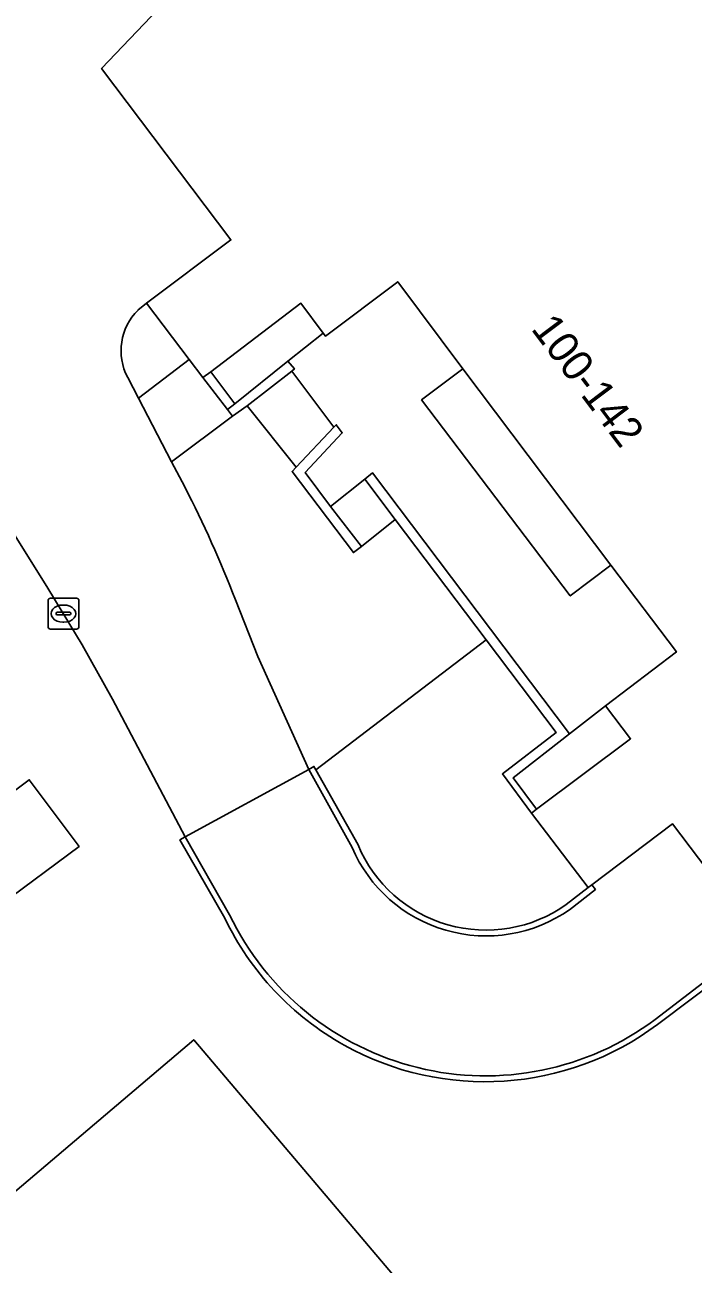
# Model space of a CAD drawing. Extents: x 159664 to 160323, y 385312 to 386115.
# Drawn here: x 160248.41 to 160270.1, y 385679.17 to 385719.4 of the extents above; entities that cross this region are included whole.
import ezdxf

# ---------------------------------------------------------------- set-up
doc = ezdxf.new("R2010")
doc.units = 0
for name, color, linetype in [('IMGEO_Erf', 7, 'Continuous'), ('IMGEO_Grasland_overig', 7, 'Continuous'), ('IMGEO_Groenvoorziening', 7, 'Continuous'), ('IMGEO_Kolk', 7, 'Continuous'), ('IMGEO_Muur', 7, 'Continuous'), ('IMGEO_Pand', 7, 'Continuous'), ('IMGEO_Pand_nummerreeks', 7, 'Continuous'), ('IMGEO_Rijbaan_lokaal_gesloten', 7, 'Continuous'), ('IMGEO_Rijbaan_lokaal_open', 7, 'Continuous'), ('IMGEO_Voetpad_gesloten', 7, 'Continuous'), ('IMGEO_Voetpad_open', 7, 'Continuous')]:
    doc.layers.add(name, color=color, linetype=linetype)

msp = doc.modelspace()

# ---------------------------------------------------------------- linework, layer by layer
at = {"layer": 'IMGEO_Erf'}
for points in [[(160266.876, 385735.19), (160264.393, 385733.512), (160252.585, 385725.7), (160246.042, 385721.322), (160246.807, 385720.18), (160248.245, 385721.253), (160251.326, 385723.587), (160252.567, 385721.898), (160255.554, 385725.077), (160256.651, 385724.048), (160264.426, 385732.287), (160272.75, 385724.372), (160285.704, 385707.218), (160290.989, 385697.019), (160273.623, 385687.905), (160272.395, 385689.541), (160268.944, 385686.952)], [(160254.898, 385690.405), (160253.446, 385692.943), (160253.619, 385693.044), (160251.255, 385697.508), (160250.277, 385699.271), (160249.155, 385701.115), (160239.467, 385716.612), (160239.203, 385716.432), (160229.319, 385709.686), (160228.116, 385708.9), (160194.996, 385688.17)], [(160226.855, 385676.268), (160230.745, 385679.398), (160229.115, 385681.462), (160231.74, 385683.535), (160234.236, 385685.506), (160235.866, 385683.442), (160239.809, 385686.456), (160238.134, 385688.577), (160240.759, 385690.65), (160243.454, 385692.779), (160245.129, 385690.658), (160246.77, 385691.949), (160245.996, 385692.985), (160248.554, 385694.896), (160250.173, 385692.729), (160247.615, 385690.818), (160213.723, 385664.117)], [(160240.294, 385673.867), (160246.675, 385680.3), (160246.795, 385680.421), (160253.895, 385686.456), (160257.769, 385681.887), (160261.002, 385678.073)]]:
    msp.add_lwpolyline(points, dxfattribs=at)
for centre, radius, start, end in [((160263.334, 385694.452), 9.357, 205.6268, 240.8523), ((160263.342, 385694.461), 9.369, 240.8394, 306.7237)]:
    msp.add_arc(centre, radius, start, end, dxfattribs=at)
at = {"layer": 'IMGEO_Grasland_overig'}
for points in [[(160251.749, 385707.952), (160252.097, 385707.282), (160253.747, 385708.533), (160252.363, 385710.359)], [(160252.363, 385710.359), (160252.084, 385710.136)]]:
    msp.add_lwpolyline(points, dxfattribs=at)
msp.add_arc((160253.38, 385708.82), 1.847, 134.5457, 208.0133, dxfattribs=at)
at = {"layer": 'IMGEO_Groenvoorziening'}
msp.add_lwpolyline([(160265.982, 385690.843), (160266.688, 385691.397), (160264.855, 385693.81), (160263.909, 385695.081), (160265.653, 385696.432), (160263.384, 385699.436), (160257.849, 385695.219), (160259.223, 385692.78)], dxfattribs=at)
msp.add_arc((160263.376, 385694.512), 4.5, 202.6371, 305.3803, dxfattribs=at)
at = {"layer": 'IMGEO_Kolk'}
for p, q in [((160249.165, 385699.859), (160249.165, 385700.711)), ((160249.24, 385700.785), (160250.092, 385700.785)), ((160249.653, 385700.565), (160249.678, 385700.565)), ((160250.166, 385700.711), (160250.166, 385699.859)), ((160249.424, 385700.279), (160249.424, 385700.291)), ((160249.862, 385700.242), (160249.464, 385700.242)), ((160249.467, 385700.328), (160249.865, 385700.328)), ((160249.908, 385700.291), (160249.908, 385700.279)), ((160250.092, 385699.785), (160249.24, 385699.785)), ((160249.676, 385700.005), (160249.651, 385700.005))]:
    msp.add_line(p, q, dxfattribs=at)
for points in [[(160249.165, 385699.859), (160249.165, 385700.711)], [(160249.24, 385700.785), (160250.092, 385700.785)], [(160250.166, 385700.711), (160250.166, 385699.859)], [(160250.092, 385699.785), (160249.24, 385699.785)]]:
    msp.add_lwpolyline(points, dxfattribs=at)
for centre, radius, start, end in [((160249.242, 385700.709), 0.0765, 91.552, 178.448), ((160249.242, 385700.709), 0.0765, 91.552, 178.448), ((160250.09, 385700.709), 0.0765, 1.552, 88.448), ((160250.09, 385700.709), 0.0765, 1.552, 88.448), ((160249.464, 385700.288), 0.0403, 85.8775, 175.7526), ((160249.461, 385700.278), 0.0366, 178.938, 274.7102), ((160249.865, 385700.285), 0.043, 264.8664, 352.4533), ((160249.869, 385700.29), 0.0386, 1.7309, 96.639), ((160249.242, 385699.861), 0.0765, 181.552, 268.448), ((160249.242, 385699.861), 0.0765, 181.552, 268.448), ((160250.09, 385699.861), 0.0765, 271.552, 358.448), ((160250.09, 385699.861), 0.0765, 271.552, 358.448)]:
    msp.add_arc(centre, radius, start, end, dxfattribs=at)
for centre, major_axis, ratio, start_param, end_param in [((160249.652, 385700.285), (-0.387, 0.002), 0.722429, 4.712389, 7.853982), ((160249.677, 385700.285), (-0.39, 0.002), 0.717154, 1.570796, 4.712389)]:
    msp.add_ellipse(centre, major_axis=major_axis, ratio=ratio, start_param=start_param, end_param=end_param, dxfattribs=at)
at = {"layer": 'IMGEO_Muur'}
for points in [[(160254.985, 385706.906), (160255.221, 385707.094), (160254.446, 385708.137), (160254.188, 385707.952)], [(160254.985, 385706.906), (160255.146, 385706.693), (160255.625, 385707.029), (160257.074, 385708.159), (160257.159, 385708.225), (160256.951, 385708.478), (160255.221, 385707.094)], [(160259.331, 385702.462), (160258.328, 385703.766), (160257.513, 385704.865), (160258.712, 385706.152), (160258.518, 385706.414), (160258.439, 385706.341), (160257.212, 385705.038), (160257.086, 385704.895), (160259.073, 385702.267)], [(160264.259, 385694.957), (160266.084, 385696.384), (160259.698, 385704.854), (160259.447, 385704.653), (160260.425, 385703.336), (160263.384, 385699.436), (160265.653, 385696.432), (160263.909, 385695.081), (160264.855, 385693.81), (160265.013, 385693.938)]]:
    msp.add_lwpolyline(points, close=True, dxfattribs=at)
for points in [[(160259.223, 385692.78), (160257.849, 385695.219), (160257.79, 385695.324), (160257.623, 385695.23), (160259.029, 385692.698)], [(160255.057, 385690.514), (160253.619, 385693.044), (160253.446, 385692.943), (160254.898, 385690.405)], [(160266.088, 385690.674), (160266.924, 385691.335), (160266.805, 385691.485), (160266.688, 385691.397), (160265.982, 385690.843)], [(160268.944, 385686.952), (160272.395, 385689.541), (160272.263, 385689.716), (160268.868, 385687.112)]]:
    msp.add_lwpolyline(points, dxfattribs=at)
for centre, radius, start, end in [((160263.382, 385694.559), 4.734, 203.1436, 304.8585), ((160263.376, 385694.512), 4.5, 202.6371, 305.3803), ((160263.361, 385694.491), 9.208, 205.5922, 306.732), ((160263.334, 385694.452), 9.357, 205.6268, 240.8523), ((160263.342, 385694.461), 9.369, 240.8394, 306.7237)]:
    msp.add_arc(centre, radius, start, end, dxfattribs=at)
at = {"layer": 'IMGEO_Pand'}
msp.add_lwpolyline([(160253.653, 385720.876), (160250.901, 385717.977), (160255.097, 385712.417), (160252.363, 385710.359), (160253.747, 385708.533), (160254.188, 385707.952), (160254.446, 385708.137), (160257.373, 385710.36), (160258.096, 385709.393), (160258.169, 385709.285), (160260.51, 385711.056), (160262.626, 385708.229), (160267.431, 385701.856), (160269.553, 385699.045), (160267.251, 385697.297), (160268.068, 385696.224), (160265.013, 385693.938), (160264.855, 385693.81), (160266.688, 385691.397), (160266.805, 385691.485), (160269.422, 385693.466), (160272.263, 385689.716)], dxfattribs=at)
for points in [[(160245.996, 385692.985), (160246.77, 385691.949), (160247.615, 385690.818), (160250.173, 385692.729), (160248.554, 385694.896)], [(160246.795, 385680.421), (160246.675, 385680.3), (160253.875, 385673.165), (160253.99, 385673.285), (160255.014, 385674.142), (160256.003, 385674.971), (160257.873, 385676.575), (160258.448, 385675.907), (160261.002, 385678.073), (160257.769, 385681.887), (160253.895, 385686.456)]]:
    msp.add_lwpolyline(points, close=True, dxfattribs=at)
at = {"layer": 'IMGEO_Rijbaan_lokaal_gesloten'}
for points in [[(160259.029, 385692.698), (160257.623, 385695.23), (160253.619, 385693.044), (160255.057, 385690.514)], [(160268.868, 385687.112), (160272.263, 385689.716), (160269.422, 385693.466), (160266.805, 385691.485), (160266.924, 385691.335), (160266.088, 385690.674)]]:
    msp.add_lwpolyline(points, dxfattribs=at)
for centre, radius, start, end in [((160263.382, 385694.559), 4.734, 203.1436, 304.8585), ((160263.361, 385694.491), 9.208, 205.5922, 306.732)]:
    msp.add_arc(centre, radius, start, end, dxfattribs=at)
at = {"layer": 'IMGEO_Rijbaan_lokaal_open'}
for points in [[(160252.084, 385710.136), (160252.363, 385710.359), (160255.097, 385712.417), (160250.901, 385717.977), (160253.653, 385720.876), (160252.789, 385721.677), (160252.567, 385721.898), (160251.326, 385723.587), (160248.245, 385721.253), (160246.807, 385720.18), (160246.984, 385719.914), (160245.557, 385718.959), (160244.747, 385720.17), (160239.467, 385716.612), (160249.155, 385701.115), (160250.277, 385699.271), (160251.255, 385697.508), (160253.619, 385693.044), (160257.623, 385695.23), (160255.973, 385698.889), (160255.245, 385700.732)], [(160253.602, 385704.399), (160253.174, 385705.209), (160252.097, 385707.282), (160251.749, 385707.952)]]:
    msp.add_lwpolyline(points, dxfattribs=at)
for centre, radius, start, end in [((160253.38, 385708.82), 1.847, 134.5457, 208.0133), ((160220.574, 385687.399), 37.147, 21.0343, 27.2352)]:
    msp.add_arc(centre, radius, start, end, dxfattribs=at)
at = {"layer": 'IMGEO_Voetpad_gesloten'}
for points in [[(160256.951, 385708.478), (160258.096, 385709.393), (160257.373, 385710.36), (160254.446, 385708.137), (160255.221, 385707.094)], [(160257.212, 385705.038), (160258.439, 385706.341), (160257.074, 385708.159), (160255.625, 385707.029)], [(160260.425, 385703.336), (160259.447, 385704.653), (160258.328, 385703.766), (160259.331, 385702.462)]]:
    msp.add_lwpolyline(points, close=True, dxfattribs=at)
at = {"layer": 'IMGEO_Voetpad_open'}
for points in [[(160266.107, 385700.858), (160261.287, 385707.223), (160262.626, 385708.229), (160260.51, 385711.056), (160258.169, 385709.285), (160258.096, 385709.393), (160256.951, 385708.478), (160257.159, 385708.225), (160257.074, 385708.159), (160258.439, 385706.341), (160258.518, 385706.414), (160258.712, 385706.152), (160257.513, 385704.865), (160258.328, 385703.766), (160259.447, 385704.653), (160259.698, 385704.854), (160266.084, 385696.384), (160267.251, 385697.297), (160269.553, 385699.045), (160267.431, 385701.856)], [(160254.188, 385707.952), (160253.747, 385708.533), (160252.097, 385707.282), (160253.174, 385705.209), (160255.146, 385706.693), (160254.985, 385706.906)], [(160267.431, 385701.856), (160262.626, 385708.229), (160261.287, 385707.223), (160266.107, 385700.858)], [(160266.084, 385696.384), (160264.259, 385694.957), (160265.013, 385693.938), (160268.068, 385696.224), (160267.251, 385697.297)]]:
    msp.add_lwpolyline(points, close=True, dxfattribs=at)
msp.add_lwpolyline([(160255.245, 385700.732), (160255.973, 385698.889), (160257.623, 385695.23), (160257.79, 385695.324), (160257.849, 385695.219), (160263.384, 385699.436), (160260.425, 385703.336), (160259.331, 385702.462), (160259.073, 385702.267), (160257.086, 385704.895), (160257.212, 385705.038), (160255.625, 385707.029), (160255.146, 385706.693), (160253.174, 385705.209), (160253.602, 385704.399)], dxfattribs=at)
msp.add_arc((160220.574, 385687.399), 37.147, 21.0343, 27.2352, dxfattribs=at)

# ---------------------------------------------------------------- texts
at = {"layer": 'IMGEO_Pand_nummerreeks'}
msp.add_text('100-142', height=1, rotation=306.9842, dxfattribs=at).set_placement((160264.813, 385709.524))

doc.saveas('drawing.dxf')
